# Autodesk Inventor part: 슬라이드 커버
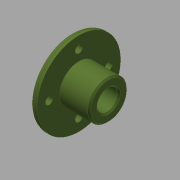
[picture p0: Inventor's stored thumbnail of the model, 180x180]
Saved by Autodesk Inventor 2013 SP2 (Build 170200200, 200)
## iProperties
Created: 2015-12
Part Number: 슬라이드 커버
Document SubType Name: Modeling
Designer: mdu
Density: 2.71 g/cm^3
Material: 알루미늄 6061
Author: mdu
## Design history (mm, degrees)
sketch "스케치1"
  geometry: L1 (-12.5, 0)-(12.5, 0); L2 (-12.5, 0)-(-12.5, 28); L3 (-12.5, 28)-(-7.5, 28); L4 (-7.5, 28)-(-7.5, 13); L5 (-7.5, 13)-(12.5, 13); L6 (12.5, 13)-(12.5, 0); 2 further points
  constraints: 12 end point, 3 perpendicular, 1 coincident, 1 horizontal, 1 midpoint, 1 parallel
  dimensions: "d1" = 56 diameter of L3 L1; "d2" = 26 diameter of L5 L1; "d5" = 5 distance of L2.end L3.end; "d32" = 20 distance of L4.end L5.end
revolve "회전1" sketch "스케치1" stored, may be unused: angle "d6" = 90 deg
sketch "스케치2" dims "d33" = 40
  geometry: 3 further points
  constraints: 2 vertical alignment, 1 coincident, 2 other
hole "구멍1" sketch "스케치2" at (0, 20) diameter "d8" = 5; stored, may be unused: countersink angle "d12" = 90 deg, drill point angle "d14" = 118 deg; dims "d9" = 6, "d10" = 8, "d11" = 4.4, "d13" = 8
hole "구멍2" diameter "d20" = 14; stored, may be unused: countersink angle "d24" = 90 deg, drill point angle "d26" = 0 deg; dims "d18" = 10, "d19" = 10, "d21" = 6, "d22" = 8, "d23" = 4.4, "d25" = 8
fillet "모깎기1" dims "d27" = 3
chamfer "모따기1" distance "d29" = 1; stored, may be unused: second distance "d30" = 2, angle "d31" = 45 deg
node "솔리드1"
pattern_circular "원형 패턴1" dims angle "d16" = 360 deg
